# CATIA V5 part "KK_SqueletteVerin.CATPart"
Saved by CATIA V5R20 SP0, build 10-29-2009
Part number: Squelette_corps_verin
Bounding box of the stored display mesh (mm): x -200 to 200, y 0 to 646.629, z -2384.658 to -1280
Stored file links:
  G:\Khaled_CFAO_2011\ST2M\ST2M_GR2\aboulegue\Khaled\CAD_thinkMOTION\KK_SqueletteVerin.CATPart
  G:\Khaled_CFAO_2011\ST2M\ST2M_GR2\aboulegue\Khaled\CAD_thinkMOTION\KK_Train_Atterrissage.CATProduct
  G:\Khaled_CFAO_2011\ST2M\ST2M_GR2\aboulegue\CFAO_aboulegue\CFAO_aboulegue_fichiers_catia\Squelette_general.CATPart
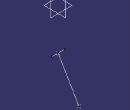
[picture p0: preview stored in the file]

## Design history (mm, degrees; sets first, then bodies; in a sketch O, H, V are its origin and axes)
Set1
  Plane1 "Plan reference": linked copy from another document
  Point1: linked copy from another document
  Point2 "Point.13": linked copy from another document
Set2 "Set_squelette_verin"
  Line1: type Normal, RefPoint Point1, RefSkin Plane1, Start -200, End 200
  Line2: type PtPt, FirstPoint Point1, SecondPoint Point2
Body1 (main body)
